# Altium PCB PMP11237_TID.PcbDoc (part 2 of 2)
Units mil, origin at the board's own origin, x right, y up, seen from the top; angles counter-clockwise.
Board outline 9200 x 5000 mil, 2 copper layers (Top Layer, Bottom Layer), stack 62 mil thick; 181 components, 96 nets, 449 pads, 4 vias.
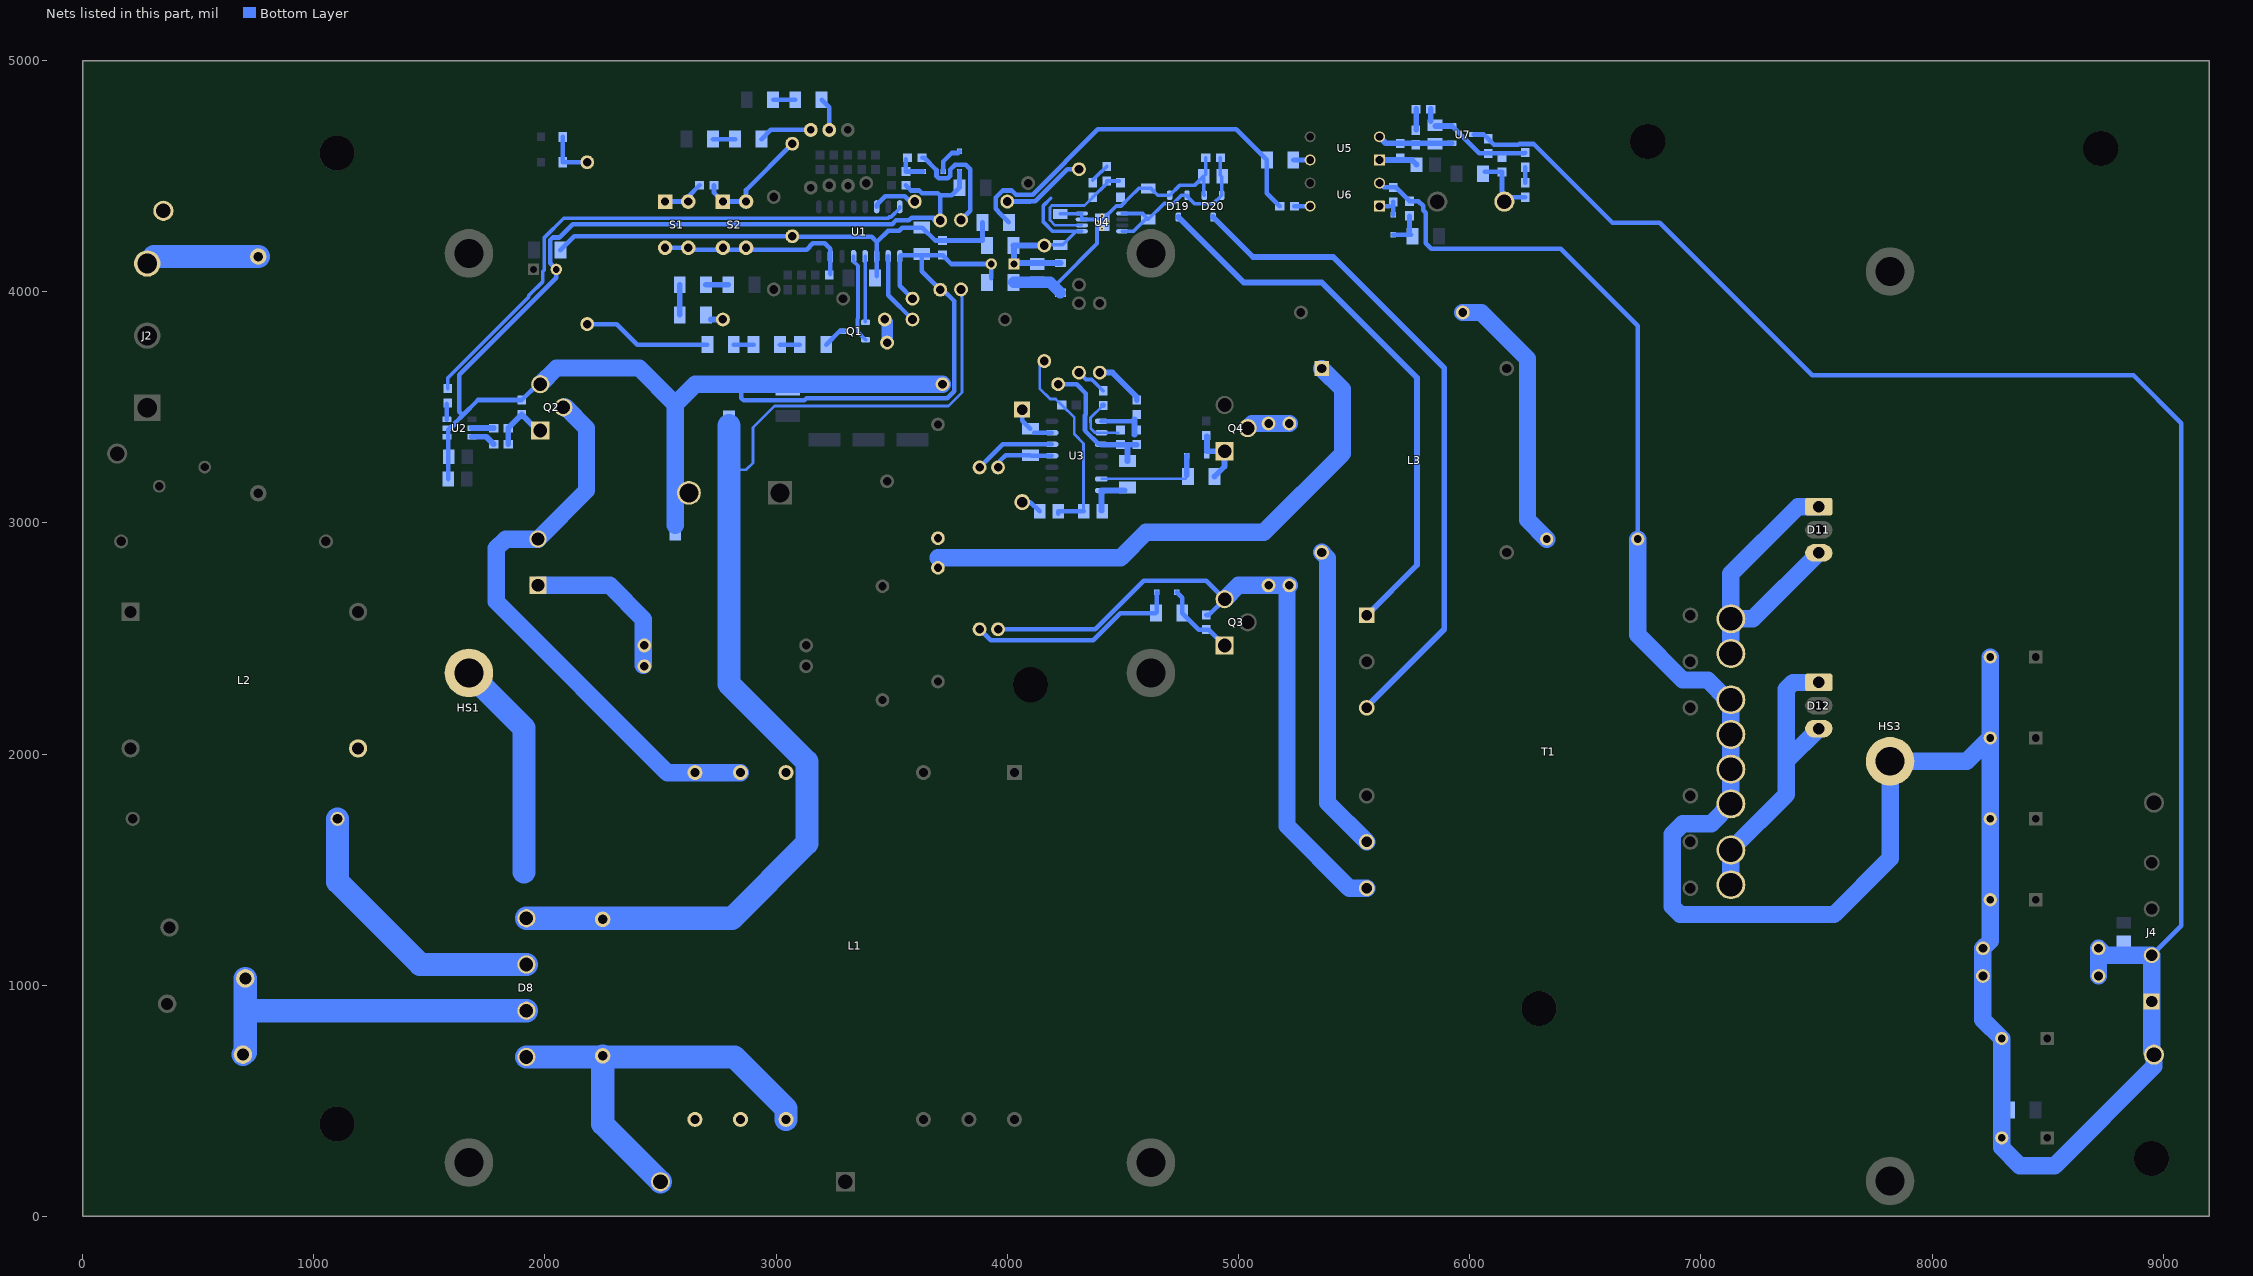
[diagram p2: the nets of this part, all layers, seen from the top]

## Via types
v1: diameter 19.68, hole 7.87, Top Layer to Bottom Layer, 4 vias

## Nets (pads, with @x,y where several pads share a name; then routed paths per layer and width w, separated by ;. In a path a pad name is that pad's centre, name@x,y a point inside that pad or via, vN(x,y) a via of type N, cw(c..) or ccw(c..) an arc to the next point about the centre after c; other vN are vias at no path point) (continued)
NetC12_2: C12.2 D8.3 L2.7 | length 1237.9
  Bottom Layer w100: C12.2@1102.91,1720 1102.91,1447.09 1460,1090 D8.3@1920,1090
NetC13_1: C13.1 D6.2 D8.1 L1.7 L1.8 L1.9 | length 1910.6
  Bottom Layer w100: D8.1@1920,690 C13.1@2250,690 ; C13.1@2250,694.72 C13.1@2250,690 ; D6.2@2500,150 2250,400 C13.1@2250,690 ; L1.9@3043,420 3043,467 2820,690 C13.1@2250,690
NetC15_1: C15.1 C38.1 C42.1 C45.1 D18.1 J14.1 R5.1 R48.2 U4.1 | length 950.5
  Bottom Layer w16: J14.1@4163.07,4203.07 C45.1@4230,4203.07 4240.07,4203.07 U4.1@4298.61,4261.61 ; 4187.58,4403.87 4156.13,4372.42 4156.13,4301.44 4195.95,4261.61 U4.1@4298.61,4261.61 ; U4.1@4322.4,4261.61 U4.1@4298.61,4261.61 ; C38.1@4370,4483.49 4406.51,4520 4408.5,4520 R48.2@4430,4541.5
  Bottom Layer w25: R5.1@4027.09,4200 J14.1@4160,4200 ; C15.1@4029.21,4120 R5.1@4029.21,4199.21 ; C15.1@4033.68,4124.47 D18.1@4230,4124.47
NetC20_2: C20.2 J27.1 | length 1177.3
  Bottom Layer w75: J27.1@5970,3910 6050,3910 6250,3710 6250,3013.15 C20.2@6333.15,2930
NetC21_2: C21.2 C27.1 L3.1 | length 2341.3
  Bottom Layer w75: 3700,2850 4490,2850 4600,2960 5110,2960 5450,3300 5450,3577.64 L3.1@5360,3667.64
NetC22_2: C22.2 J14.2 R36.1 R38.2 | length 842.5
  Bottom Layer w12: J14.2@4140,3680 4140,3581.89 4185.64,3536.25 4209.25,3536.25 C22.2@4235.5,3510 4290.13,3455.38 4290.13,3383.66 4330,3343.79 R38.2@4330,3050
  Bottom Layer w20: R36.1@4220,3040 R36.1@4220,3050 R38.2@4330,3050
NetC26_1: C26.1 D10.1 U3.13 | length 173.2
  Bottom Layer w20: D10.1@4064.57,3490 4064.57,3442.52 C26.1@4100,3407.09 ; C26.1@4117.09,3390 U3.13@4192.72,3390
NetC26_2: C26.2 J13.2 U3.11 | length 229.3
  Bottom Layer w20: 3970,3270 3992.91,3292.91 C26.2@4100,3292.91 ; C26.2@4102.91,3290 U3.11@4192.72,3290
NetC35_1: C35.1 R38.1 U3.7 | length 187.1
  Bottom Layer w25: R38.1@4407.28,3052.72 U3.7@4407.28,3140 C35.1@4507.09,3140
NetC35_2: C35.2 C36.2 C37.1 J11.1 U3.3 | length 614.4
  Bottom Layer w12: U3.3@4395.66,3340 U3.3@4407.28,3340
  Bottom Layer w20: J11.1@4220,3600 4300,3600 4340.13,3559.87 4340.13,3468.85 4336.13,3464.85 4336.13,3400.11 4340.13,3396.11 4340.13,3395.53 U3.3@4395.66,3340
  Bottom Layer w25: U3.3@4408.78,3338.5 C36.2@4490,3338.5 C37.1@4560,3338.5 ; C35.2@4520,3267.09 4520,3335.7
NetC36_1: C36.1 R41.1 U3.2 | length 248.9
  Bottom Layer w12: R41.1@4413.54,3508.5 4360,3454.97 4360,3434.7 4360.91,3433.79 4360.91,3409.09 4380,3390 U3.2@4407.28,3390 C36.1@4478.5,3390
  Bottom Layer w25: R41.1@4413.54,3508.5 R41.1@4415,3508.5
NetC37_2: C37.2 R39.1 U3.1 | length 201.2
  Bottom Layer w20: U3.1@4407.28,3440 4541.5,3440
  Bottom Layer w25: 4550,3381.5 4550,3448.5
NetC38_2: C38.2 R48.1 R55.1 U4.2 | length 553.3
  Bottom Layer w12: U4.2@4322.4,4287.2 4206.95,4287.2 4184.63,4309.53 4184.63,4364.33 4192.76,4372.46 4333.95,4372.46 C38.2@4370,4408.5
  Bottom Layer w16: C38.2@4370,4408.5 4430,4468.5 R48.1@4430,4478.5 R55.1@4482.99,4478.5
NetC39_1: C39.1 R47.1 R50.2 TP28.1 | length 264.4
  Bottom Layer w20: R47.1@6065.59,4518.5 R50.2@6140,4518.5 TP28.1@6140,4400 ; TP28.1@6168.5,4408.5 C39.1@6240,4408.5
NetC39_2: C39.2 R51.1 | length 67
  Bottom Layer w20: C39.2@6240,4471.5 R51.1@6240,4538.5
NetC40_1: C40.1 C43.1 D19.2 D20.2 R54.2 U4.5 U4.8 | length 807.6
  Bottom Layer w16: U4.8@4497.6,4261.61 4545.91,4261.61 4597.37,4313.07 C43.1@4610,4313.07 ; U4.5@4497.6,4338.39 4584.69,4338.39 C43.1@4610,4313.07 ; C40.1@4921.5,4503.31 R54.2@4921.5,4580 ; C40.1@4927.4,4497.4 D20.2@4927.4,4417.24 4890.16,4380 4810,4380 4777.4,4412.6 D19.2@4777.4,4417.24 4753.08,4417.24 4717.53,4381.69 4678.61,4381.69 C43.1@4610,4313.07
NetC40_2: C40.2 C42.2 C43.2 C45.2 D18.2 D19.1 D20.1 R9.1 R54.1 R55.2 U4.3 U4.4 U4.9 | length 1440.2
  Bottom Layer w16: 4220,4040 4388.35,4208.35 v1(4388.35,4300) ; C45.2@4230,4336.93 4320.94,4336.93 U4.4@4322.4,4338.39 ; U4.4@4322.4,4335.47 U4.3@4322.4,4312.8 U4.9@4397.2,4312.8 ; U4.9@4410,4310 4470.87,4370.87 4492.36,4370.87 4530,4408.5 4568.43,4446.93 C43.2@4610,4446.93 4621.5,4446.93 4651.18,4417.24 D19.1@4702.6,4417.24 4745.35,4460 4810,4460 C40.2@4850,4500 4850,4419.84 D20.1@4852.6,4417.24 ; C40.2@4858.5,4508.5 R54.1@4858.5,4580
  Bottom Layer w50: R9.1@4027.09,4040 4185.53,4040 D18.2@4230,3995.53
  other v1: 4410,4272.05 4431.65,4300 4410,4327.95
NetC41_1: C41.1 C46.1 R50.1 R51.2 R58.2 U7.2 | length 489.4
  Bottom Layer w20: U7.2@5922.76,4717.4 6041.65,4598.5 R58.2@6080,4598.5 6237.01,4598.5 R51.2@6240,4601.5
  Bottom Layer w25: C41.1@5831.5,4738.5 C46.1@5831.5,4790 ; C41.1@5852.6,4717.4 U7.2@5922.76,4717.4
NetC41_2: C41.2 R49.1 R56.1 U5.2 U7.1 | length 324.1
  Bottom Layer w25: U5.2@5610,4670 5637.4,4642.6 U7.1@5922.76,4642.6
NetC46_2: C46.2 R56.2 | length 89.4
  Bottom Layer w25: R56.2@5768.5,4700.62 C46.2@5768.5,4790
NetC47_1: C47.1 D17.1 R45.1 | length 146.2
  Bottom Layer w20: D17.1@5670,4246.69 R45.1@5746.22,4246.69 ; R45.1@5740,4258.5 C47.1@5740,4328.5
NetD1_1: D1.1 D2.1 J6.2 | length 215.8
  Bottom Layer w20: D1.1@2077.24,4670 D2.1@2077.24,4560 J6.2@2183,4560
NetD4_1: D4.1 R20.2 R21.1 | length 128.2
  Bottom Layer w20: R20.2@3561.5,4572.99 R21.1@3561.5,4520 D4.1@3636.69,4520
NetD4_2: D4.2 D5.1 | length 131.2
  Bottom Layer w20: D4.2@3723.31,4520 3723.31,4563.31 3760,4600 3786.69,4600 D5.1@3793.31,4606.61
NetD7_1: D7.1 J1.1 J3.1 | length 716.5
  Bottom Layer w75: D7.1@1970,2730 2280,2730 2426,2584 J1.1@2426,2384
NetD7_2: D7.2 L1.5 L1.6 Q2.2 | length 2493.4
  Bottom Layer w75: Q2.2@2080,3500 2090,3500 2180,3410 2180,3140 D7.2@1970,2930 1830,2930 1790,2890 1790,2660 2530,1920 L1.6@2649,1920 L1.5@2846,1920
NetD8_2: D8.2 RT1.2 RT2.2 | length 1540.1
  Bottom Layer w100: RT2.2@694,700 704,710 RT1.2@704,1030 ; 714,890 D8.2@1920,890
NetD9_1: D9.1 J12.1 R35.1 | length 917.5
  Bottom Layer w20: J12.1@3880,2540 3927.87,2492.13 4371.55,2492.13 4489.42,2610 R35.1@4642.6,2610 ; R35.1@4646.38,2613.78 D9.1@4646.38,2700
NetD9_2: D9.2 Q3.1 R35.2 R37.2 | length 341.1
  Bottom Layer w20: D9.2@4732.99,2700 4756.77,2676.22 R35.2@4756.77,2610 4828.27,2538.5 R37.2@4860,2538.5 4871.5,2538.5 Q3.1@4940,2470
NetD10_2: D10.2 R36.2 | length 92
  Bottom Layer w20: D10.2@4064.57,3090 4100,3090 R36.2@4140,3050
NetD11_1: D11.1 D11.3 T1.13 T1.14 | length 1343.2
  Bottom Layer w75: T1.14@7130,2435 T1.13@7130,2585 ; D11.3@7510,2870 7225,2585 T1.13@7130,2585 ; D11.1@7510,3070 7420,3070 7130,2780 T1.13@7130,2585
NetD12_1: D12.1 D12.3 T1.19 T1.20 | length 1294.8
  Bottom Layer w75: T1.20@7130,1435 T1.19@7130,1585 7370,1825 7370,1970 ; D12.3@7510,2110 7370,1970 ; D12.1@7510,2310 7400,2310 7370,2280 7370,1970
NetD13_1: D13.1 R42.1 U3.6 | length 451.4
  Bottom Layer w10: U3.6@4407.28,3190 4407.28,3191.38 R42.1@4773.32,3191.38
  Bottom Layer w25: R42.1@4776.69,3205.98 D13.1@4776.69,3290
NetD13_2: D13.2 Q4.1 R42.2 R43.1 | length 269.5
  Bottom Layer w25: R43.1@4863.31,3375.2 4863.31,3310 Q4.1@4940,3310 4940,3243.88 R42.2@4896.49,3200.37
NetD17_2: D17.2 R57.2 U6.1 | length 96.7
  Bottom Layer w20: U6.1@5610,4370 R57.2@5651.5,4370 ; D17.2@5670,4333.31 R57.2@5670,4388.5
NetD19_3: D19.3 T1.1 | length 2438.1
  Bottom Layer w25: D19.3@4740,4322.76 5022.76,4040 5360,4040 5772.5,3627.5 5772.5,2817.5 T1.1@5555,2600
NetD20_3: D20.3 T1.3 | length 2874.1
  Bottom Layer w25: D20.3@4890,4322.76 5062.76,4150 5410,4150 5890,3670 5890,2540 T1.3@5555,2205
NetF1_2: F1.2 J2.3 TP15.1 | length 492.3
  Bottom Layer w100: J2.3@280,4122 309.81,4151.81 F1.2@760,4151.81
NetJ5_1: J5.1 U1.2 | length 316.2
  Bottom Layer w20: U1.2@3485,4152.72 3485,3985 J5.1@3590,3880
NetJ6_1: J6.1 R1.1 | length 556.4
  Bottom Layer w20: J6.1@2183,3860 2310,3860 2398.76,3771.24 R1.1@2702.67,3771.24
NetJ7_1: J7.1 J8.1 J13.1 Q3.3 R37.1 T1.6 | length 3000.2
  Bottom Layer w20: J13.1@3960,2540 4380,2540 4590,2750 4860,2750 Q3.3@4940,2670 4871.5,2601.5 R37.1@4860,2601.5
  Bottom Layer w75: Q3.3@4940,2670 5000,2730 J7.1@5130,2730 J8.1@5220,2730 ; J8.1@5210,2720 5210,1690 5480,1420 T1.6@5555,1420
NetJ7_2: J7.2 J8.2 Q4.2 | length 188.3
  Bottom Layer w75: Q4.2@5040,3410 5060,3430 J7.2@5130,3430 J8.2@5220,3430
NetJ9_2: J9.2 R39.2 | length 217
  Bottom Layer w25: J9.2@4400,3650 4455,3650 4560,3545 R39.2@4560,3531.5
NetJ10_2: J10.2 R41.2 | length 137.5
  Bottom Layer w16: J10.2@4310,3650 4340,3620 4365.12,3620 4413.63,3571.5 R41.2@4415,3571.5
NetJ12_2: J12.2 U3.12 | length 354.1
  Bottom Layer w20: J12.2@3880,3240 3980,3340 U3.12@4192.72,3340
NetJ16_1: J16.1 R15.2 S2.1 S2.4 | length 518.8
  Bottom Layer w20: R15.2@2731.5,4460 2731.5,4428.5 S2.1@2770,4390 S2.4@2870,4390 2870,4440 J16.1@3070,4640
NetJ17_1: J17.1 R20.1 | length 546.6
  Bottom Layer w20: R20.1@3631.5,4580 3640,4580 3693.62,4526.38 3693.62,4500.79 3704.09,4490.31 3743.12,4490.31 3743.12,4490.92 3752.99,4500.79 3752.99,4528.58 3774.09,4549.68 3820.32,4549.68 3840,4530 3840,4350 J17.1@3800,4310
NetJ18_1: J18.1 J19.2 | length 104.1
  Bottom Layer w50: J19.2@3470,3880 3480,3870 J18.1@3480,3780
NetJ19_1: J19.1 R10.1 | length 52.9
  Bottom Layer w25: R10.1@2717.09,3880 J19.1@2770,3880
NetJ20_1: J20.1 J23.2 | length 368
  Bottom Layer w20: J20.1@4000,4390 4100,4390 4102.13,4392.13 4121.55,4392.13 4259.42,4530 J23.2@4310,4530
NetJ20_2: J20.2 U1.14 | length 199.1
  Bottom Layer w20: U1.14@3435,4367.28 3435,4376 3472.7,4413.7 3556.3,4413.7 3580,4390 J20.2@3600,4390
NetL3_6: L3.6 T1.5 | length 1333.1
  Bottom Layer w75: L3.6@5360,2872.36 5385,2847.36 5385,1790 T1.5@5555,1620
NetQ1_1: Q1.1 U1.4 | length 283.1
  Bottom Layer w16: Q1.1@3385,3869.65 U1.4@3385,4152.72
NetQ1_2: Q1.2 U1.5 | length 384
  Bottom Layer w16: U1.5@3335,4152.72 3335,4131.26 3354.38,4111.88 3354.38,3885.02 3351.68,3882.33 3351.68,3849.78 3354.38,3847.09 3354.38,3825.46 Q1.2@3387.24,3792.6
NetQ1_3: Q1.3 R3.2 | length 100.3
  Bottom Layer w20: R3.2@3216.84,3771.24 3275.6,3830 Q1.3@3292.76,3830
NetQ2_1: Q2.1 R26.2 R27.2 R28.1 | length 249.6
  Bottom Layer w25: R27.2@1841.5,3340 R26.2@1841.5,3410 R28.1@1900,3468.5 Q2.1@1968.5,3400
NetR1_2: R1.2 R2.1 | length 85.8
  Bottom Layer w20: R1.2@2816.84,3771.24 R2.1@2902.67,3771.24
NetR2_2: R2.2 R3.1 | length 85.8
  Bottom Layer w20: R2.2@3016.84,3771.24 R3.1@3102.67,3771.24
NetR6_2: R6.2 R8.1 | length 229.5
  Bottom Layer w20: R8.1@2937.09,4660 2977.09,4700 R6.2@3150,4700
NetR7_1: R7.1 R8.2 | length 95.8
  Bottom Layer w20: R7.1@2727.09,4660 R8.2@2822.91,4660
NetR10_2: R10.2 R11.1 | length 130
  Bottom Layer w25: R10.2@2582.91,3900 R11.1@2582.91,4030
NetR11_2: R11.2 R12.1 | length 95.8
  Bottom Layer w25: R11.2@2697.09,4030 R12.1@2792.91,4030
NetR15_1: R15.1 S1.1 S1.4 | length 168.6
  Bottom Layer w20: S1.1@2520,4390 S1.4@2620,4390 ; S1.4@2620,4411.5 R15.1@2668.5,4460
NetR16_2: R16.2 R44.2 R52.1 | length 1718.8
  Bottom Layer w20: R16.2@4007.09,4300 3960.83,4346.26 3960.83,4347.68 3950,4358.5 3950,4407.7 3980.17,4437.87 4019.83,4437.87 4037.7,4420 4110,4420 4392.13,4702.13 4990.79,4702.13 R44.2@5122.91,4570 5122.91,4425.59 R52.1@5178.5,4370
NetR17_1: R17.1 R18.2 | length 95.8
  Bottom Layer w20: R17.1@2987.09,4830 R18.2@3082.91,4830
NetR18_1: R18.1 R19.2 | length 143.6
  Bottom Layer w20: R18.1@3197.09,4830 3230,4797.09 R19.2@3230,4700
NetR25_1: R25.1 U2.6 | length 67
  Bottom Layer w20: U2.6@1575.87,3447.4 R25.1@1575.87,3514.37
NetR26_1: R26.1 U2.2 | length 94.4
  Bottom Layer w25: U2.2@1684.13,3410 R26.1@1778.5,3410
NetR27_1: R27.1 U2.3 | length 107.9
  Bottom Layer w25: U2.3@1684.13,3372.6 1745.91,3372.6 R27.1@1778.5,3340
NetR44_1: R44.1 U5.4 | length 72.9
  Bottom Layer w20: R44.1@5237.09,4570 U5.4@5310,4570
NetR46_1: R46.1 R49.2 U5.1 | length 168.3
  Bottom Layer w25: U5.1@5610,4570 5750,4570 R46.1@5770,4550
NetR52_2: R52.2 U6.4 | length 68.5
  Bottom Layer w20: R52.2@5241.5,4370 U6.4@5310,4370
PFCCS: C13.2 D8.4 HS1.2 J17.2 L1.4 R30.2 R31.2 R32.2 | length 5901.5
  Bottom Layer w12: 2826.14,3230 2870,3230 2899.67,3259.67 2899.67,3412.66 2993.13,3506.13 3746.13,3506.13 3803.87,3563.87 J17.2@3803.87,4006.13
  Bottom Layer w100: HS1.2@1671.34,2351.14 1910,2112.48 1910,1490 ; D8.4@1920,1290 2810,1290 3133.35,1613.35 3133.35,1966.65 2796.14,2303.86 R32.2@2796.14,2990 R30.2@2796.14,3260 R31.2@2796.14,3420
PFCGD: R25.2 U1.16 | length 2421.8
  Bottom Layer w16: R25.2@1580,3581.5 1580,3627.17 1930.54,3977.71 1930.54,3983.95 1991.27,4044.68 1991.27,4088.06 1997.75,4094.54 1997.75,4234.54 2081.21,4318 3485.72,4318 3490.58,4322.87 3496.47,4322.87 3535,4361.4 U1.16@3535,4367.28
PGND: C1.2 C2.1 C4.2 C10.1 C14.2 C15.2 C17.2 C18.2 C19.2 D5.2 J11.2 J15.1 J24.1 J24.2 Q2.3 R9.2 R28.2 R29.2 R30.1 R31.1 R32.1 R33.2 R34.2 R59.1 U1.1 U2.4 U2.5 | length 8566.3
  Bottom Layer w20: C18.2@1582.34,3190 1582.34,3403.52 1596.53,3417.72 1601.78,3417.72 1613.43,3429.36 1613.43,3434.31 1645.07,3465.95 ; Q2.3@1980,3600 1968.5,3600 R28.2@1900,3531.5 1710.61,3531.5 1645.07,3465.95 ; 2850,3600 2850,3540 2860,3530 3121.42,3530 3131.42,3540 3740,3540 3770,3570 3770,3960 3721.5,4008.5 J24.1@3710,4008.5 3630,4088.5 C2.1@3630,4158.5 ; C10.1@3561.5,4460 3583.62,4437.87 3619.83,4437.87 3631.01,4426.69 3700,4426.69 3710,4416.69 ; J15.1@3590,3970 3535,4025 U1.1@3535,4152.72 3540.79,4158.5 C2.1@3630,4158.5 ; J11.2@3710,3610 J11.2@3720,3600 ; R59.1@3792.91,4450 3759.61,4416.69 3710,4416.69 ; R59.1@3793.31,4450.39 D5.2@3793.31,4520 ; R9.2@3930.79,4057.87 C15.2@3930.79,4120 3758.5,4120 C1.2@3720,4158.5 C2.1@3630,4158.5 ; 1645.07,3465.95 1630,3481.02 1630,3640.58 2049.21,4059.79 C4.2@2049.21,4096.79 2023.62,4122.38 2023.62,4223.82 2034.09,4234.29 2061.97,4234.29 2119.8,4292.13 3502.32,4292.13 3518.7,4308.5 3574.13,4308.5 3586.18,4320.55 3684.29,4320.55 3684.29,4308.5 J24.2@3710,4308.5 3710,4416.69
  Bottom Layer w75: Q2.3@1980,3600 2050,3670 2407.72,3670 2563.86,3513.86 ; R32.1@2563.86,2990 R30.1@2563.86,3260 R31.1@2563.86,3420 2563.86,3513.86 ; J11.2@3720,3600 2850,3600 2650,3600 2563.86,3513.86
PSON: R23.2 S1.3 S1.6 S2.3 S2.6 U1.7 | length 852.6
  Bottom Layer w20: S1.3@2520,4182.13 S1.3@2520,4190 S1.6@2620,4190 ; S1.6@2620,4182.13 3132.13,4182.13 3159.21,4209.21 3210.79,4209.21 3235,4185 U1.7@3235,4152.72 R23.2@3235,4076.5
SEC_0V: C20.1 C28.2 C29.2 C30.2 C31.2 C32.2 C33.2 C34.2 C47.2 HS3.2 J4.1 J4.2 J25.1 J25.2 J26.1 J26.2 R40.1 R57.1 R58.1 T1.15 T1.16 T1.17 T1.18 TP26.1 U6.2 U7.3 | length 16145.8
  Bottom Layer w20: U6.2@5610,4470 5628.5,4451.5 R57.1@5670,4451.5 5680,4451.5 C47.2@5740,4391.5 5778.5,4391.5 5798.63,4371.37 5798.63,4353.2 5810,4341.83 5810,4209.8 5834.09,4185.71 6394.29,4185.71 6726.85,3853.15 C20.1@6726.85,2930 ; U7.3@6017.24,4680 6061.5,4680 R58.1@6080,4661.5 6105.43,4636.06 6210.9,4636.06 6213.9,4639.06 6276.57,4639.06 6617.76,4297.87 6821.55,4297.87 7481.55,3637.87 8871.55,3637.87 9077.87,3431.55 9077.87,1257.87 J4.2@8950,1130
  Bottom Layer w75: C20.1@6726.85,2930 6726.85,2515.9 6922.12,2320.63 7029.37,2320.63 7115,2235 T1.15@7130,2235 T1.16@7130,2085 T1.17@7130,1935 T1.18@7130,1785 7044.37,1699.37 6922.12,1699.37 6875.63,1652.88 6875.63,1340.63 6910,1306.25 7576.25,1306.25 7818.66,1548.66 HS3.2@7818.66,1968.86 8150.43,1968.86 C30.2@8251.57,2070 ; C29.2@8251.57,2420 C30.2@8251.57,2070 ; J26.1@8720,1040 J25.1@8720,1160 8750,1130 J4.2@8950,1130 J4.1@8950,930 TP26.1@8950,710 ; TP26.1@8960,700 8960,650 8530,220 8380,220 8301.57,298.43 C33.2@8301.57,340 C28.2@8301.57,770 8220,851.57 J26.2@8220,1040 J25.2@8220,1160 8251.57,1191.57 C32.2@8251.57,1370 C31.2@8251.57,1720 C30.2@8251.57,2070
VCC: C1.1 C2.2 C3.2 J16.2 R4.1 R5.2 R16.1 U1.3 | length 2141.6
  Bottom Layer w20: R4.1@2067.09,4180 2126.46,4239.37 3070,4239.37 J16.2@3070,4230 ; J16.2@3070,4240 3072.91,4237.09 3412.91,4237.09 3435,4215 ; C3.2@3435,4067.91 U1.3@3435,4152.72 3435,4215 ; C2.2@3630,4277.09 3545.93,4277.09 3533.09,4264.25 3484.25,4264.25 3435,4215 ; C2.2@3632.91,4277.09 3688.5,4221.5 C1.1@3720,4221.5 R5.2@3891.42,4221.5 ; R5.2@3892.91,4220 R16.1@3892.91,4300
pads on no net: H3.0 H3.MH H4.0 H4.MH H9.0 H9.MH H10.0 H10.MH H16.0 H16.MH H21.0 H21.MH H22.0 H22.MH HS1.1 HS1.3 HS2.2 HS2.3 HS3.1 HS3.3 J2.2 L1.10 L1.11 L1.12 L3.7 L3.14 T1.2 T1.4 T1.7 T1.8 T1.9 T1.10 T1.11 T1.12 U1.15 U3.4 U3.8 U3.9 U3.10 U3.14 U4.6 U4.7

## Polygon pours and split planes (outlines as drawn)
NetF1_2 on Bottom Layer "F1_2" (solid, remove dead copper, pour order 2): 150,4060 130,4080 130,4140 130,4300 130,4400 150,4420 190,4420 800,4420 820,4400 820,4340 820,4080 800,4060
AC1 on Bottom Layer "AC1" (solid, remove dead copper, pour order 4): 100,3570 80,3550 80,3510 80,3370 80,2540 100,2520 200,2520 350,2520 370,2540 370,2630 370,3550 350,3570
AC2 on Bottom Layer "AC2" (solid, remove dead copper, pour order 8): 520,3320 500,3300 500,3240 500,3180 630,3050 1120,2560 1240,2560 1260,2580 1260,2660 1260,2950 890,3320
NetC12_1 on Bottom Layer "C12_1" (solid, remove dead copper, pour order 10): 30,2100 10,2080 10,2060 10,1960 10,970 10,410 10,30 30,10 90,10 450,10 470,30 470,90 470,890 470,2080 450,2100
NetD8_2 on Bottom Layer "D8_2" (solid, remove dead copper, pour order 12): 1970,920 1950,940 1930,940 1750,940 1370,940 920,1390 800,1390 510,1390 490,1370 490,1350 490,30 510,10 610,10 920,10 940,30 940,160 940,430 1120,610 1390,610 1610,610 1840,840 1850,850 1950,850 1970,870
NetC12_2 on Bottom Layer "C12_2" (solid, remove dead copper, pour order 14): 1040,2080 1060,2100 1090,2100 1240,2100 1320,2100 1340,2080 1340,2060 1340,1620 1820,1140 1950,1140 1970,1120 1970,1060 1950,1040 1930,1040 1440,1040 1400,1080 1040,1440 1040,2080
NetC13_1 on Bottom Layer "C13_1" (solid, remove dead copper, pour order 16): 1890,740 1870,720 1870,690 1870,660 1870,570 2060,380 2340,100 2910,100 3080,100 3100,120 3100,177.56 3100,500 2860,740
NetD7_2 on Bottom Layer "D7_2" (solid, remove dead copper, pour order 20): 2890,1930 2860,1960 2850,1960 2770,1960 2581.59,1960 1851.59,2690 1851.59,2770 1851.59,2831.59 1870,2850 1890,2850 1950,2850 2030,2930 2230,3130 2230,3420 2160,3490 2110,3540 2060,3540 2040,3520 2040,3490 2040,3480 2060,3460 2080,3440 2080,3380 2080,3320 2080,3200 1940,3060 1860,3060 1750,3060 1730,3040 1690,3000 1690,2650 1730,2610 2410,1930 2500,1840 2860,1840 2890,1870
NetD7_1 on Bottom Layer "D7_1" (solid, remove dead copper, pour order 22): 1940,2780 1930,2770 1930,2748.78 1935.14,2743.65 1930,2738.51 1930,2700 1940,2690 1960,2690 2280,2370 2320,2330 2430,2330 2450,2330 2470,2350 2470,2380 2470,2600 2290,2780 2280,2780
BULK on Bottom Layer "Bulk" (solid, remove dead copper, pour order 24): 2970,3190 2960,3180 2960,3150 2960,3070 2970,3060 3050,2980 3050,2850 3050,2490 3050,2370 3190,2230 3650,1770 4215,1770 4830,1770 5120,2060 5120,2110 5120,2590 5100,2610 5090,2610 5020.7,2610 5000,2589.3 5000,2560 5000,2550 5010,2540 5030,2520 5030,2510 5030,2347.52 4782.48,2100 4340,2100 4060,2100 3830,2330 3790,2370 3630,2370 3450,2370 3220,2600 3220,3020 3080,3160 3080,3180 3070,3190
NetL3_6 on Bottom Layer "L3_6" (solid, remove dead copper, pour order 26): 5330,2910 5320,2900 5320,2880 5320,2840 5320,2800 5340,2780 5340,2760 5340,2630 5340,2270 5340,1760 5520,1580 5590,1580 5610,1600 5610,1640 5610,1680 5500,1790 5500,2290 5500,2820 5410,2910
NetJ7_1 on Bottom Layer "J7_1" (solid, remove dead copper, pour order 34): 4920,2630 4900,2650 4900,2690 4900,2750 4920,2770 5010,2770 5250,2770 5270,2750 5270,2730 5270,2650 5270,2360 5270,2230 5270,2190 5270,1950 5270,1730 5360,1640 5510,1490 5590,1490 5610,1470 5610,1440 5610,1390 5590,1370 5450,1370 5370,1370 5170,1570 5170,1590 5170,2140 5170,2610 5120,2660 5040,2660 5000,2660 4990,2660 4960,2630
NetC21_2 on Bottom Layer "C21_2" (solid, remove dead copper, pour order 36): 5330,3710 5310,3690 5310,3670 5310,3640 5310,3294.57 5165.43,3150 5065.43,3050 4630,3050 4600,3050 4510,2960 4480,2930 3780,2930 3740,2970 3700,2970 3680,2970 3660,2950 3660,2930 3660,2790 3680,2770 3720,2770 4510,2770 4620,2880 4650,2880 5150,2880 5440,3170 5520,3250 5520,3370 5520,3690 5500,3710
NetJ7_2 on Bottom Layer "J7_2" (solid, remove dead copper, pour order 40): 5000,3430 5000,3410 5000,3390 5010,3380 5080,3310 5140,3310 5240,3310 5260,3330 5260,3400 5260,3450 5240,3470 5180,3470 5040,3470
LLC_RCS on Bottom Layer "LLC_RCS" (solid, remove dead copper, pour order 44): 3000,3490 2970,3460 2970,3420 2970,3320 2990,3300 3030,3300 3210,3300 3530,3300 3550,3280 3560,3270 3560,3250 3560,3160 3510,3110 3400,3000 3400,2790 3400,2700 3420,2680 3480,2680 3590,2680 3610,2700 3610,2730 3610,2970 3740,3100 3790,3150 3790,3250 3790,3270 4010,3490 4010,3517.07 4376.83,3150.23 4376.83,3125.26 4376.83,3123.17 4390,3110 4407.28,3110 4590,3110 4980,3500 5310,3830 5310,3890 5310,3950 5290,3970 5230,3970 4980,3970 4770,4180 4680,4270 4600,4270 4580,4250 4455,4125 4455,3950 4455,3945 4390,3880 4380,3880 3860,3880 3840,3860 3840,3550 3760,3470 3680,3470 3640,3430 3630,3420 3600,3420 3590,3430 3590,3460.31 3590,3470 3570,3490
AGND on Bottom Layer "AGND" (solid, remove dead copper, pour order 46): 3270,4200 3260,4190 3260,4177.99 3261,4176.99 3260,4175.99 3260,4140 3260,4051.3 3248.7,4040 3230,4040 2970,4040 2950,4020 2950,4010 2950,3850 2970,3830 3000,3830 3320.31,3830 3340,3849.69 3340,3880 3340,4000 3340,4100 3320,4120 3310,4130 3310,4170 3310,4190 3300,4200
AGND1 on Bottom Layer "AGND1" (solid, remove dead copper, pour order 48): 3510,4570 3520,4580 3520,4600 3520,4630 3480,4670 3160,4670 2980,4490 2950,4460 2950,4390 2950,4380 2960,4370 2990,4370 3310,4370 3520,4580
NetC20_2 on Bottom Layer "C20_2" (solid, remove dead copper, pour order 50): 5920,3970 5900,3950 5900,3910 5900,3860 5900,3790 6000,3690 6000,3500 6000,2950 6060,2890 6240,2890 6350,2890 6370,2910 6370,2950 6370,3790 6190,3970
NetD12_1 on Bottom Layer "D12_1" (solid, remove dead copper, pour order 32): 7090,1370 7060,1400 7040,1420 7020,1440 7020,1570 7020,1580 7100,1660 7120,1660 7200,1740 7220,1760 7220,2130 7220,2310 7320,2410 7350,2440 7410,2440 7570,2440 7590,2420 7590,2410 7590,2380 7590,2280 7580,2270 7560,2270 7510,2270 7480,2270 7450,2270 7430,2250 7430,2230 7430,2171.15 7451.15,2150 7530,2150 7580,2150 7590,2140 7590,2130 7590,2060 7590,1670 7290,1370
NetD11_1 on Bottom Layer "D11_1" (solid, remove dead copper, pour order 28): 7080,2370 7000,2450 7000,2530 7000,2540 7000,2810 7000,3160 7020,3180 7030,3180 7560,3180 7580,3160 7580,3130 7580,3040 7570,3030 7550,3030 7460,3030 7440,3010 7430,3000 7430,2990 7430,2950 7430,2940 7460,2910 7470,2910 7550,2910 7570,2890 7570,2880 7570,2560 7550,2540 7420,2540 7340,2540 7170,2370
+VOUT on Bottom Layer "+Vout" (solid, remove dead copper, pour order 30): 7470,3010 7451.15,2991.15 7451.15,2990 7451.15,2969.99 7451.15,2950 7451.15,2948.85 7470,2930 7490,2930 7560,2930 7590,2900 7590,2890 7590,2830 7590,2762.51 7590,2570 7590,2490 7590,2480 7620,2450 7620,2390 7620,2270 7600,2250 7560,2250 7470,2250 7450,2230 7450,2220 7450,2190 7470,2170 7490,2170 7730,2170 8080,2520 8290,2520 8340,2470 8340,2450 8340,2280 8340,1500 8340,1240 8340,900 8340,870 8380,830 8380,800 8380,390 8470,300 8510,300 8520,300 8540,320 8630,410 8630,780 8630,1200 8680,1250 8710,1250 8990,1250 9010,1270 9010,1280 9010,1460 9010,1820 9010,2240 8240,3010
SEC_0V on Bottom Layer "SGND" (solid, remove dead copper, pour order 54): 9190,30 9170,10 9150,10 8550,10 6710,10 6690,30 6690,70 6690,100 6690,2370 6690,2880 6690,3870 6690,3880 6620,3950 6390,4180 5840,4180 5760,4180 5600,4340 5587.11,4352.89 5587.11,4450 5587.11,4967.11 5610,4990 5630,4990 6120,4990 9170,4990 9190,4970
NetC40_1 on Bottom Layer "C40_1" (solid, remove dead copper, pour order 38): 4480.31,4344.51 4480.31,4318.91 4480.31,4255.71 4497.11,4255.71 4550.71,4255.71 4580,4285 4585,4290 4610,4290 4650,4290 4720,4360 4730,4370 4960,4370 4980,4390 4980,4440 4980,4600 4960,4620 4950,4620 4920,4620 4900,4600 4900,4598.7 4900,4580 4900,4520 4900,4414.61 4880,4394.61 4832.9,4394.61 4832.9,4397.1 4810,4420 4790,4440 4760,4440 4750,4430 4710,4390 4630,4390 4590,4390 4550,4350 4540,4340 4534.02,4340
NetC15_1 on Bottom Layer "C15_1" (solid, remove dead copper, pour order 42): 4010,4100 4050,4100 4192.93,4100 4250,4100 4310,4160 4350,4200 4350,4260 4350,4263.12 4345.41,4267.71 4339.78,4267.71 4256.09,4267.71 4250,4261.61 4210,4261.61 4195.95,4261.61 4167.57,4290 4160,4297.57 4160,4340 4220,4400 4331.32,4400 4371.32,4440 4441.3,4440 4470,4440 4490,4460 4490,4510 4480,4520 4470,4520 4360,4520 4350,4510 4350,4500 4350,4481.5 4241.5,4481.5 4130,4370 4130,4270 4120,4260 4100,4240 4080,4240 4020,4240 4010,4230
NetC40_2 on Bottom Layer "C40_2" (solid, remove dead copper, pour order 58): 4010,4070 4010,4010 4050,3970 4110,3970 4250,3970 4260,3980 4642.13,4362.13 4680.94,4362.13 4852.95,4362.13 4880.83,4390 4880,4390.83 4880,4490 4880,4660 4860,4680 4830,4680 4460,4680 4010,4230
NetC35_2 on Bottom Layer "C35_2" (solid, remove dead copper, pour order 60): 4180,3634 4184,3630 4267,3630 4390,3630 4570,3450 4570,3370 4570,3250 4550,3230 4360,3230 4340.31,3230 4280.31,3290 4260,3310.31 4260,3420 4260,3487.07 4180,3567.07
PFCCS on Bottom Layer "PFCCS" (solid, remove dead copper, pour order 62): 1890,1240 1860,1270 1860,1320 1860,1430 1860,1560 1910,1610 2030,1610 2840,1610 3010,1780 3010,1800 3010,1950 2900,2060 2710,2250 2710,3130 2710,3462.99 2730,3482.99 2732.93,3485.92 2791.97,3485.92 2844.08,3485.92 2850,3480 2860,3470 2860,3460 2860,3360 2860,3260 2860,3120 2860,3060 2950,2970 2970,2950 2970,2770 2970,2360 3300,2030 3300,1730 3300,1460 3080,1240
PGND on Bottom Layer "PGND" (solid, remove dead copper, pour order 64): 2690,2870 2670,2850 2630,2850 2450,2850 1620,2850 1470,3000 1470,3030 1470,4040 1740,4310 2030,4310 2480,4310 3160,4990 3170,4990 5300,4990 5320,4970 5320,4940 5320,4470 4810,3960 3780,3960 3740,3960 3730,3950 3730,3940 3750,3920 3750,3830 3750,3710 3750,3578.7 3738.37,3567.07 3735.44,3570 3513.46,3570 2800,3570 2690,3460

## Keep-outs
Keep-Out Layer:
  text ".Layer_Name" at 577,-858.49 h60

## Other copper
Top Layer:
  text ".Layer_Name" at 577,-858.49 h60
Bottom Layer:
  text ".Layer_Name" at 577,-858.49 h60

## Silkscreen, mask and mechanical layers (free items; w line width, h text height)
Top Overlay:
  lines w10: 3810,3970 3810,3960 3820,3950 3840,3950
  text ".PRJ_Number" at 5860,120 h60
  text ".PCB_Rev" at 6460,120 h60
  text ".Layer_Name" at 577,-858.49 h60
Bottom Overlay:
  lines w10: 3270,4640 3270,4790 3300,4820 ; 3500,4570 3500,4670 ; 4460,3600 4480,3620 4480,3650 ; 5560,4530 5720,4530 ; 5570,4420 5630,4420 ; 5620,4720 5630,4710 5670,4710 5690,4690 ; 5700,4730 5700,4720 5710,4710 5720,4710 ; 5790,4320 5910,4320 ; 5890,4770 5910,4790 5910,4850 ; 3280,4830 3290,4820 3480,4820 3510,4850 3510,4900 3470,4940 3310,4940 3280,4910 3280,4830
  text ".Layer_Name" at 577,-858.49 h60
Top Paste:
  text ".Layer_Name" at 577,-858.49 h60
Bottom Paste:
  text ".Layer_Name" at 577,-858.49 h60
Top Solder:
  text ".Layer_Name" at 577,-858.49 h60
  text ".Layer_Name" at 577,-858.49 h60
Bottom Solder:
  text ".Layer_Name" at 577,-858.49 h60
Drill Guide:
  text ".Layer_Name" at 577,-858.49 h60
M1 Board Outline:
  the board outline again, w10
  text ".Layer_Name" at 577,-858.49 h60
M2 Board Dimensions:
  rectangle: 125,-400 500,-275
  rectangle: 0,-275 125,-150
  lines w7: 0,-275 1000,-275 ; 125,-400 125,-150 ; 250,-400 250,-150 ; 500,-400 500,-150 ; 750,-400 750,-150 ; 0,-400 0,-150 1000,-150 1000,-400 0,-400
  text ".Layer_Name" at 577,-858.49 h60
M3 3D STEP Top:
  text ".Layer_Name" at 577,-858.49 h60
M4 3D STEP Bottom:
  text ".Layer_Name" at 577,-858.49 h60
M5 Assembly Top:
  lines w10: -292,-930.17 6308,-930.17 ; -292,-726.83 6310,-726.83 ; -292,-523.5 -292,-1133.5 3713,-1133.5 6310,-1133.5 6310,-523.5 -291.5,-523.5 -291.5,-1133.5 1284,-1133.5 ; 2173,-1133.5 2173,-523.5 ; 3440,-726.83 3440,-523.5 ; 4280,-726.83 4280,-523.5 ; 4902,-1140 4902,-937.17
  text "COMPONENTS MARKED 'DNP' SHOULD NOT BE POPULATED." at 1153.5,-318.5 h60
  text "ASSEMBLY VARIANT:" at 1153,-434 h60
  text ".VariantName" at 2189,-434 h60
  text "PCB VIEWED FROM TOP SIDE" at -228.5,-655.67 h60
  text "BOARD #:" at 2248,-655.67 h60
  text ".PRJ_Number" at 2793.5,-655.67 h60
  text "REV:" at 3638,-655.67 h60
  text ".PCB_Rev" at 3929.5,-655.67 h60
  text "SVN REV:" at 4476,-655.67 h60
  text ".VersionControl_RevNumber" at 4982,-655.67 h60
  text "TID #:" at 2248,-859 h60
  text ".TID" at 2793.5,-859 h60
  text "PLOT NAME =" at -228.5,-1064.34 h60
  text ".plot_File_Name" at 577,-1064.34 h60
  text "GENERATED    :" at 2250,-1064.34 h60
  text ".Print_Date" at 3119.5,-1064.34 h60
  text ".Print_Time" at 3848.5,-1064.34 h60
  text "TEXAS INSTRUMENTS" at 5113,-1064.34 h60
M6 Assembly Bottom:
  lines w10: -292.5,-727.33 6309.5,-727.33 ; -290.5,-930.67 6309.5,-930.67 ; 1115.5,-1140.5 1115.5,-937.67 ; 1737.5,-727.33 1737.5,-524 ; 2577.5,-727.33 2577.5,-524 ; 3844.5,-1134 3844.5,-524 ; 4733.5,-1134 6309,-1134 6309,-524 -292.5,-524 -292.5,-1134 2304.5,-1134 6309.5,-1134 6309.5,-524
  text "COMPONENTS MARKED 'DNP' SHOULD NOT BE POPULATED." at 6102,-318 h60
  text ".VariantName" at 5058,-434 h60
  text "ASSEMBLY VARIANT:" at 6097,-434 h60
  text ".VersionControl_RevNumber" at 1035.5,-656.17 h60
  text "SVN REV:" at 1541.5,-656.17 h60
  text ".PCB_Rev" at 2088,-656.17 h60
  text "REV:" at 2379.5,-656.17 h60
  text ".PRJ_Number" at 3224,-656.17 h60
  text "BOARD #:" at 3769.5,-656.17 h60
  text "PCB VIEWED FROM BOTTOM SIDE" at 6246,-656.17 h60
  text ".TID" at 3224,-859.5 h60
  text "TID #:" at 3769.5,-859.5 h60
  text "TEXAS INSTRUMENTS" at 904.5,-1064.84 h60
  text ".Print_Time" at 2169,-1064.84 h60
  text ".Print_Date" at 2898,-1064.84 h60
  text "GENERATED    :" at 3767.5,-1064.84 h60
  text ".plot_File_Name" at 5440.5,-1064.84 h60
  text "PLOT NAME =" at 6246,-1064.84 h60
M9 Title Sheet:
  drawing of 57 lines, arcs and shapes, not listed
  text "1" at 739.84,8036.5 h70
  text "2" at 3235.5,8036.5 h70
  text "3" at 5724.84,8036.5 h70
  text "4" at 8231.51,8036.5 h70
  text "5" at 10730.5,8036.5 h70
  text "6" at 13235.5,8036.5 h70
  text "A" at -416.5,6893.5 h70
  text "A" at 14383.5,6893.5 h70
  text "B" at -416.5,4513.5 h70
  text "B" at 14383.5,4513.5 h70
  text "C" at -416.5,2138.5 h70
  text "C" at 14383.5,2138.5 h70
  text "PROJECT TITLE:" at 11343.5,277.5 h45
  text ".PRJ_Title" at 11393.5,144.17 h70
  text "DESIGNED FOR:" at 11343.5,-23.5 h45
  text ".PRJ_Customer" at 11393.5,-163.5 h70
  text "D" at -416.5,-231.5 h70
  text "D" at 14383.5,-231.5 h70
  text "FILE NAME:" at 11343.5,-323.5 h45
  text ".PCB_File_Name_No_Path" at 11393.5,-443.5 h70
  text "Texas Instruments (TI) and/or its licensors do not warrant the accuracy or completeness of this specification" at 6374,-605.34 h45
  text "ENGINEER:" at 11343.5,-613.5 h45
  text "LAYOUT BY:" at 12848.5,-613.5 h45
  text "or any information contained therein. TI and/or its licensors do not warrant that this design will meet" at 6329.01,-718 h45
  text ".PRJ_Engineer" at 11393.5,-768.49 h70
  text ".PCB_Layout" at 12899,-768.49 h70
  text "the specifications, will be suitable for your application or fit for any particular purpose, or will operate in" at 6329.01,-830.67 h45
  text ".Layer_Name" at 577,-858.49 h60
  text "ALTIUM DESIGNER VERSION:" at 12848.5,-923.5 h45
  text "an implementation. TI and/or its licensors do not warrant that the design is production worthy. You should" at 6329.01,-943.33 h45
  text "completely validate and test your design implementation to confirm the system functionality for your application." at 6374,-1056 h45
  text ".print_Scale" at 11393.5,-1056.83 h70
  text ".Application_BuildNumber" at 12899,-1056.83 h70
  text "1" at 739.84,-1263.5 h70
  text "2" at 3235.5,-1263.5 h70
  text "3" at 5724.84,-1263.5 h70
  text "4" at 8231.51,-1263.5 h70
  text "5" at 10730.5,-1263.5 h70
  text "6" at 13235.5,-1263.5 h70
M10 Fab Notes:
  drawing of 185 lines, arcs and shapes, not listed
  text "DESIGN INFORMATION" at 12381.02,5910 h60
  text "MIN. TRACK WIDTH:" at 11736.46,5730 h60
  text "10" at 12832.7,5730 h60
  text "MIL" at 12987.46,5730 h60
  text "MIN. CLEARANCE:" at 11736.46,5598 h60
  text "0.2" at 12772.7,5598 h60
  text "mm" at 12987.46,5598 h60
  text "MIN. VIA PAD SIZE:" at 11736.46,5466 h60
  text "10" at 12802.71,5466 h60
  text "MIL" at 12987.46,5466 h60
  text "0.05mm (2MIL)" at 12431.46,5324.29 h60
  text "MINIMUM ANNULAR RING" at 11407.23,5320 h60
  text "EXTERNAL" at 13139.46,5320 h60
  text "PER" at 11607.23,5202 h60
  text "IPC-D-275 CLASS 2 LEVEL C" at 11827.23,5202 h60
  text "MIL, HOLES" at 13315.46,5089.71 h60
  text "+/-" at 12923,5089 h60
  text "+/-" at 13777,5089 h60
  text "REGISTRATION TOLERANCES:" at 11407.23,5084 h60
  text "METAL" at 12607,5084 h60
  text "5" at 13183.2,5084 h60
  text "3" at 14016.2,5084 h60
  text "MIL" at 14132.46,5084 h60
  text "MATERIAL:" at 11332.46,4874.54 h60
  text "FR-4 High Tg" at 12318.9,4734.21 h60
  text "FR-408" at 11753.46,4725.64 h60
  text "X" at 12165.46,4725.64 h60
  text "OTHER" at 13241.46,4725.64 h60
  text "62 MIL (1.6mm) +/-10%" at 12073.56,4562.92 h60
  text "THICKNESS:" at 11407.23,4558.64 h60
  text "X" at 11945.4,4558.64 h60
  text "OTHER" at 13358.46,4558.64 h60
  text "TOLERANCE:" at 11407.23,4400.64 h60
  text "X" at 12246.53,4400.64 h60
  text "ANSI IPC-6012 TYPE 3 CLASS 2" at 12433.48,4400.64 h60
  text "OTHER +/-" at 12433.46,4244.64 h60
  text "BOW & TWIST:" at 11407.23,4087.64 h60
  text "X" at 12246.53,4087.64 h60
  text "ANSI IPC-6012 TYPE 3 CLASS 2" at 12433.48,4087.64 h60
  text "OTHER +/-" at 12433.46,3929.13 h60
  text "DRILLING:" at 11332.46,3790.64 h60
  text "REFERENCE:" at 11407.23,3673.64 h60
  text "X" at 12055.46,3673.64 h60
  text "AS SHOWN" at 12242.46,3673.64 h60
  text "X" at 12956.46,3673.64 h60
  text "NC_DRILL FILES" at 13093.46,3673.64 h60
  text "PTH MIN COPPER THICKNESS:" at 11407.23,3515.64 h60
  text "X" at 12757.46,3515.64 h60
  text "1MIL" at 12894.46,3515.64 h60
  text "OTHER" at 13391.46,3515.64 h60
  text "BOARD FINISH:" at 11332.46,3356.64 h60
  text "SILKSCREEN:" at 11487.68,3238.64 h60
  text "X" at 12436.46,3238.64 h60
  text "TOP" at 12562.46,3238.64 h60
  text "X" at 12946.46,3238.64 h60
  text "BOTTOM" at 13073.46,3238.64 h60
  text "SILKSCREEN COLOR:" at 11487.68,3071.64 h60
  text "X" at 12435.42,3071.64 h60
  text "WHITE" at 12562.46,3071.64 h60
  text "OTHER" at 13073.46,3071.64 h60
  text "SOLDER RESIST COLOR:" at 11487.68,2901.64 h60
  text "X" at 12055.42,2742.44 h60
  text "GREEN" at 12182.46,2742.44 h60
  text "BLUE" at 12773.46,2742.44 h60
  text "OTHER" at 13311.46,2742.44 h60
  text "IMMERSION GOLD (ENIG)" at 12393.46,2553.92 h60
  text "ENEPIG" at 13731,2550.64 h60
  text "SURFACE FINISH:" at 11332.46,2549.64 h60
  text "IMM. TIN/SILVER OR EQUIV" at 11662,2392.64 h60
  text "OTHER" at 13093.46,2392.64 h60
  text "X" at 11500,2390 h60
  text "ARRAY/PANEL:" at 11332.46,2213.64 h60
  text "CUT AND TRIM PER MECH LAYER 1" at 12393.46,2209.35 h60
  text "N.C. ROUTE" at 12393.46,2057.64 h60
  text "X" at 13072.46,2057.64 h60
  text "V. SCORE" at 13259.46,2057.64 h60
  text "CERTIFICATION:" at 11332.46,1920.64 h60
  text "MATERIALS AND WORKMANSHIP FOR ALL PCBS" at 12057.46,1920.64 h60
  text "TO MEET OR EXCEED THE REQUIREMENTS OF:" at 12057.46,1822.64 h60
  text "X" at 11683.96,1686.13 h60
  text "ANSI IPC-A-600F CLASS ->" at 11822.96,1686.13 h60
  text "X" at 13462.02,1686.13 h60
  text "2" at 13580.96,1686.14 h60
  text "1" at 13265.96,1684.64 h60
  text "3" at 13934.96,1684.64 h60
  text "X" at 11686.02,1526.64 h60
  text "UL 94V-0" at 11822.96,1526.64 h60
  text "X" at 12498.02,1526.64 h60
  text "RoHS" at 12634.96,1526.64 h60
  text "OTHER" at 13279.36,1526.64 h60
  text "PER ORDER" at 13676.42,1526.64 h60
  text "ADDITIONAL REQUIREMENTS:" at 11332.46,1385.64 h60
  text "MICROSECTION:" at 11407.23,1270.64 h60
  text "YES" at 12312.96,1270.64 h60
  text "REQUIRED" at 13174.46,1114.49 h60
  text "BARE BOARD ELEC. TEST:" at 11407.23,1111.64 h60
  text "NONE" at 12712.96,1111.64 h60
  text "PER ORDER" at 13766.46,1111.64 h60
  text "X" at 12590,1110 h60
  text "MANUFACTURER'S UL:" at 11407.23,954.64 h60
  text "RAIL" at 12572.96,950.35 h60
  text "METAL" at 13064.77,950.35 h60
  text "X" at 13440,950 h60
  text "SILK" at 13576.46,950.35 h60
  text ".Layer_Name" at 577,-858.49 h60
M11 Gerber Information:
  lines w10: -292,-930.17 6308,-930.17 ; -292,-726.83 6310,-726.83 ; -292,-523.5 -292,-1133.5 3713,-1133.5 6310,-1133.5 6310,-523.5 -291.5,-523.5 -291.5,-1133.5 1284,-1133.5 ; 2173,-1133.5 2173,-523.5 ; 3440,-726.83 3440,-523.5 ; 4280,-726.83 4280,-523.5 ; 4902,-1140 4902,-937.17
  text "ALL ARTWORK VIEWED FROM TOP SIDE" at -228.5,-655.67 h60
  text "BOARD #:" at 2248,-655.67 h60
  text ".PRJ_Number" at 2793.5,-655.67 h60
  text "REV:" at 3638,-655.67 h60
  text ".PCB_Rev" at 3929.5,-655.67 h60
  text "SVN REV:" at 4476,-655.67 h60
  text ".VersionControl_RevNumber" at 4982,-655.67 h60
  text "LAYER NAME =" at -228.5,-858.49 h60
  text "TID #:" at 2248,-859 h60
  text ".TID" at 2793.5,-859 h60
  text "PLOT NAME =" at -228.5,-1064.34 h60
  text ".plot_File_Name" at 577,-1064.34 h60
  text "GENERATED    :" at 2250,-1064.34 h60
  text ".Print_Date" at 3119.5,-1064.34 h60
  text ".Print_Time" at 3848.5,-1064.34 h60
  text "TEXAS INSTRUMENTS" at 5113,-1064.34 h60
M12 Stackup:
  drawing of 191 lines, arcs and shapes, not listed
  text "Layer" at 9790.58,7830 h60
  text "Name" at 10200.49,7830 h60
  text "Material" at 11130.23,7830 h60
  text "Thickness" at 11990,7830 h60
  text "Constant" at 12639.84,7830 h60
  text "Board Layer Stack" at 13209.7,7830 h60
  text "1" at 9790.58,7710 h60
  text "Top Overlay" at 10200.49,7710 h60
  text "2" at 9790.58,7590 h60
  text "Top Solder" at 10200.49,7590 h60
  text "Solder Resist" at 11130.23,7590 h60
  text "0.40mil" at 11990,7590 h60
  text "3.5" at 12639.84,7590 h60
  text "3" at 9790.58,7470 h60
  text "Top Layer" at 10200.49,7470 h60
  text "Copper" at 11130.23,7470 h60
  text "1.40mil" at 11990,7470 h60
  text "4" at 9790.58,7350 h60
  text "Dielectric1" at 10200.49,7350 h60
  text "FR-4" at 11130.23,7350 h60
  text "59.20mil" at 11990,7350 h60
  text "4.8" at 12639.84,7350 h60
  text "5" at 9790.58,7230 h60
  text "Bottom Layer" at 10200.49,7230 h60
  text "Copper" at 11130.23,7230 h60
  text "1.40mil" at 11990,7230 h60
  text "6" at 9790.58,7110 h60
  text "Bottom Solder" at 10200.49,7110 h60
  text "Solder Resist" at 11130.23,7110 h60
  text "0.40mil" at 11990,7110 h60
  text "3.5" at 12639.84,7110 h60
  text "7" at 9790.58,6990 h60
  text "Bottom Overlay" at 10200.49,6990 h60
  text ".Layer_Name" at 577,-858.49 h60
M13 Component Bodies Top:
  text ".Layer_Name" at 577,-858.49 h60
M14 Component Bodies Bottom:
  text ".Layer_Name" at 577,-858.49 h60
M15 Courtyards Top:
  text ".Layer_Name" at 577,-858.49 h60
M16 Courtyards Bottom:
  text ".Layer_Name" at 577,-858.49 h60
Drill Drawing:
  drawing of 166 lines, arcs and shapes, not listed
  text "Symbol" at 9479.68,5905.38 h72
  text "Quantity" at 9805.51,5905.38 h72
  text "Finished Hole Size" at 10162.62,5905.38 h72
  text "Plated" at 10824.62,5905.38 h72
  text "Hole Type" at 11108.98,5905.38 h72
  text "I" at 9470.35,5768.38 h49.82
  text "7" at 9805.51,5755.92 h60
  text "152.00mil (3.861mm)" at 10162.62,5755.92 h60
  text "NPTH" at 10824.62,5755.92 h60
  text "Round" at 11108.98,5755.92 h60
  text "4" at 9805.51,5606.46 h60
  text "7.87mil (0.200mm)" at 10162.62,5606.46 h60
  text "PTH" at 10824.62,5606.46 h60
  text "Round" at 11108.98,5606.46 h60
  text "4" at 9805.51,5457 h60
  text "29.53mil (0.750mm)" at 10162.62,5457 h60
  text "PTH" at 10824.62,5457 h60
  text "Round" at 11108.98,5457 h60
  text "6" at 9805.51,5307.54 h60
  text "32.00mil (0.813mm)" at 10162.62,5307.54 h60
  text "PTH" at 10824.62,5307.54 h60
  text "Round" at 11108.98,5307.54 h60
  text "22" at 9805.51,5158.09 h60
  text "33.46mil (0.850mm)" at 10162.62,5158.09 h60
  text "PTH" at 10824.62,5158.09 h60
  text "Round" at 11108.98,5158.09 h60
  text "8" at 9805.51,5008.63 h60
  text "35.00mil (0.889mm)" at 10162.62,5008.63 h60
  text "PTH" at 10824.62,5008.63 h60
  text "Round" at 11108.98,5008.63 h60
  text "8" at 9805.51,4859.17 h60
  text "35.43mil (0.900mm)" at 10162.62,4859.17 h60
  text "PTH" at 10824.62,4859.17 h60
  text "Round" at 11108.98,4859.17 h60
  text "J" at 9470.35,4722.16 h49.82
  text "22" at 9805.51,4709.71 h60
  text "37.00mil (0.940mm)" at 10162.62,4709.71 h60
  text "PTH" at 10824.62,4709.71 h60
  text "Round" at 11108.98,4709.71 h60
  text "K" at 9470.35,4572.71 h49.82
  text "28" at 9805.51,4560.25 h60
  text "38.00mil (0.965mm)" at 10162.62,4560.25 h60
  text "PTH" at 10824.62,4560.25 h60
  text "Round" at 11108.98,4560.25 h60
  text "11" at 9805.51,4410.79 h60
  text "39.37mil (1.000mm)" at 10162.62,4410.79 h60
  text "PTH" at 10824.62,4410.79 h60
  text "Round" at 11108.98,4410.79 h60
  text "4" at 9805.51,4261.33 h60
  text "40.16mil (1.020mm)" at 10162.62,4261.33 h60
  text "PTH" at 10824.62,4261.33 h60
  text "Round" at 11108.98,4261.33 h60
  text "2" at 9805.51,4111.87 h60
  text "41.00mil (1.041mm)" at 10162.62,4111.87 h60
  text "PTH" at 10824.62,4111.87 h60
  text "Round" at 11108.98,4111.87 h60
  text "4" at 9805.51,3962.42 h60
  text "41.34mil (1.050mm)" at 10162.62,3962.42 h60
  text "PTH" at 10824.62,3962.42 h60
  text "Round" at 11108.98,3962.42 h60
  text "2" at 9805.51,3812.96 h60
  text "42.08mil (1.069mm)" at 10162.62,3812.96 h60
  text "PTH" at 10824.62,3812.96 h60
  text "Round" at 11108.98,3812.96 h60
  text "2" at 9805.51,3663.5 h60
  text "45.28mil (1.150mm)" at 10162.62,3663.5 h60
  text "PTH" at 10824.62,3663.5 h60
  text "Round" at 11108.98,3663.5 h60
  text "12" at 9805.51,3514.04 h60
  text "45.30mil (1.151mm)" at 10162.62,3514.04 h60
  text "PTH" at 10824.62,3514.04 h60
  text "Round" at 11108.98,3514.04 h60
  text "L" at 9470.35,3377.04 h49.82
  text "4" at 9805.51,3364.58 h60
  text "49.21mil (1.250mm)" at 10162.62,3364.58 h60
  text "PTH" at 10824.62,3364.58 h60
  text "Round" at 11108.98,3364.58 h60
  text "6" at 9805.51,3215.12 h60
  text "50.00mil (1.270mm)" at 10162.62,3215.12 h60
  text "PTH" at 10824.62,3215.12 h60
  text "Round" at 11108.98,3215.12 h60
  text "A" at 9470.35,3078.12 h49.82
  text "4" at 9805.51,3065.66 h60
  text "51.18mil (1.300mm)" at 10162.62,3065.66 h60
  text "PTH" at 10824.62,3065.66 h60
  text "Round" at 11108.98,3065.66 h60
  text "B" at 9470.35,2928.66 h49.82
  text "4" at 9805.51,2916.2 h60
  text "52.00mil (1.321mm)" at 10162.62,2916.2 h60
  text "PTH" at 10824.62,2916.2 h60
  text "Round" at 11108.98,2916.2 h60
  text "C" at 9470.35,2779.2 h49.82
  text "2" at 9805.51,2766.75 h60
  text "55.12mil (1.400mm)" at 10162.62,2766.75 h60
  text "PTH" at 10824.62,2766.75 h60
  text "Round" at 11108.98,2766.75 h60
  text "D" at 9470.35,2629.74 h49.82
  text "13" at 9805.51,2617.29 h60
  text "59.06mil (1.500mm)" at 10162.62,2617.29 h60
  text "PTH" at 10824.62,2617.29 h60
  text "Round" at 11108.98,2617.29 h60
  text "E" at 9470.35,2480.28 h49.82
  text "2" at 9805.51,2467.83 h60
  text "62.99mil (1.600mm)" at 10162.62,2467.83 h60
  text "PTH" at 10824.62,2467.83 h60
  text "Round" at 11108.98,2467.83 h60
  text "M" at 9470.35,2330.82 h49.82
  text "6" at 9805.51,2318.37 h60
  text "63.00mil (1.600mm)" at 10162.62,2318.37 h60
  text "PTH" at 10824.62,2318.37 h60
  text "Round" at 11108.98,2318.37 h60
  text "F" at 9470.35,2181.37 h49.82
  text "2" at 9805.51,2168.91 h60
  text "82.68mil (2.100mm)" at 10162.62,2168.91 h60
  text "PTH" at 10824.62,2168.91 h60
  text "Round" at 11108.98,2168.91 h60
  text "N" at 9470.35,2031.91 h49.82
  text "3" at 9805.51,2019.45 h60
  text "84.65mil (2.150mm)" at 10162.62,2019.45 h60
  text "PTH" at 10824.62,2019.45 h60
  text "Round" at 11108.98,2019.45 h60
  text "G" at 9470.35,1882.45 h49.82
  text "8" at 9805.51,1869.99 h60
  text "102.40mil (2.601mm)" at 10162.62,1869.99 h60
  text "PTH" at 10824.62,1869.99 h60
  text "Round" at 11108.98,1869.99 h60
  text "H" at 9470.35,1732.99 h49.82
  text "9" at 9805.51,1720.54 h60
  text "125.00mil (3.175mm)" at 10162.62,1720.54 h60
  text "PTH" at 10824.62,1720.54 h60
  text "Round" at 11108.98,1720.54 h60
  text "209 Total" at 9805.51,1571.08 h60
  text ".Layer_Name" at 577,-858.49 h60

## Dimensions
0,0 to 9200,0 on M2 Board Dimensions
0,0 to 0,5000 on M2 Board Dimensions
0,-400 to 1000,-400 on M2 Board Dimensions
